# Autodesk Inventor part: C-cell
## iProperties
Shininess: 64.0
Angle Display Precision: 2
Document Length Units: 11272
Document Angle Units: 11279
Document Time Units: 11290
Document Mass Units: 11286
Document Length Units Precision: 3
Document Angle Units Precision: 2
Created: 2002-02
Part Number: C-cell
Document SubType Name: Modeling
Designer: Ron Crain
Catalog Web Link: http://www.arken.net
Density: 0.0
Volumn: 0.0
Area: 0.0
PropertySet Name: Model Information
Control State: 0
Master: False
Checked Out: False
Author: Ron Crain
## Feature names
1. Revolution1
2. Revolution2
3. Fillet1
